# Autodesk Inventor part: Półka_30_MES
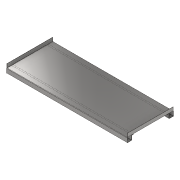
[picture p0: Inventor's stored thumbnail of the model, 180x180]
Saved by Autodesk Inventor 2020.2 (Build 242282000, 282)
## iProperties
Manager: www.cadconsulting.pl
Company: Fabian Stasiak CAD Consulting
Created: 2020-03
Part Number: Półka_30_MES
Material: Stal
Document SubType Name: Konstrukcja blachowa
Designer: F.Stasiak
Density: 7.85 g/cm^3
Sheet Metal Rule: Blacha stalowa 1.0 mm/Spoina liniowa
Appearance: Częściowo polerowany
Flat Pattern Width: 40.3896 cm
Flat Pattern Length: 68.6524 cm
Flat Pattern Area: 2772.84 cm^2
Sheet Metal Width: 403,896 mm
Sheet Metal Length: 686,524 mm
Sheet Metal Area: 277283,962 mm^2
Catalog Web Link: www.expertbooks.pl
Author: F.Stasiak
Subject: Zbiór ćwiczeń. Autodesk Inventor 2020. Kurs Professional
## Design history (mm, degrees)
node "Powierzchnia1"
  sketch "Szkic1"
    geometry: L1 (325, -125)-(-325, -125); L2 (-325, -125)-(-325, 125); L3 (-325, 125)-(325, 125); L4 (325, 125)-(325, -125); L5 (325, -125)-(-325, 125); L6 (-325, -125)-(325, 125); 1 further point
    constraints: 12 end point, 2 midpoint, 2 parallel, 1 horizontal, 1 perpendicular
    dimensions: "d0" = 650 distance of L2.end L3.end; "d1" = 250 distance of L1.end L2.end
node "Kołnierz1"
node "Kołnierz2"
node "Kołnierz3"
node "Kołnierz4"
mirror "Odbij1"
node "Kołnierz5"
sketch "Szkic11"
  geometry: L1 (0, -21)-(650, -21) reference; L2 (650, 0)-(650, -21) reference; L3 (650, 0)-(0, 0) reference; L4 (0, 0)-(0, -21) reference; L5 (650, -225)-(0, -225) reference; L6 (0, -246)-(0, -225) reference; L7 (650, -246)-(0, -246) reference; L8 (650, -246)-(650, -225) reference; L9 (0, 0)-(650, 0) reference; L10 (15, 0)-(15, -21); L11 (0, -21)-(650, -21) reference; L12 (0, -225)-(650, -225) reference; L13 (15, -225)-(15, -246); L14 (635, 0)-(635, -21); L15 (635, -225)-(635, -246); L16 (2, -246)-(648, -246) reference; 1 further point
  constraints: 8 end point, 8 point on line, 3 collinear, 2 perpendicular, 1 vertical
  dimensions: "d58" = 15 distance between parallel lines of L10 L4; "d59" = 15 distance between parallel lines of L2 L14 (= d58)
  node "Pętla rzutowana1"
  node "Pętla rzutowana2"
feature "Podział5"
feature "Podział6"
feature "Podział7"
feature "Podział8"
node "Bryła1"
feature "Płyta1" dims "d2" = 1 (= Grubość)
sketch "Szkic2"
  geometry: L1 through (-325, 0) direction (1, 0); L2 through (0, 12.5) direction (0, 1); L3 (0, 25)-(-650, 25); L4 (-650, 25)-(-650, 0)
  constraints: 6 end point, 1 horizontal, 1 perpendicular, 1 vertical
feature "Płyta2" dims "d2" = 1 (= Grubość), "d3" = 1 (= SzerokośćGięciaPodcięcia), "d4" = 0.5 (= GłębokośćGięciaPodcięcia), "d5" = 2 (= MinimalnaPozostałość), "d6" = 1 (= PromieńPrzejścia), "d9" = 25, "d10" = 90 deg, "d11" = 1 (= PromieńGięcia), "d12" = 4 (= RozmiarPodcięciaNarożnika), "d13" = 1 (= Wielk_odstępu), "d14" = 1 (= Rozmiar_promienia_Jacobiego), "OdstępPołączenia" = 0.01
feature "Zagięcie1" dims "d2" = 1 (= Grubość), "d3" = 1 (= SzerokośćGięciaPodcięcia), "d4" = 0.5 (= GłębokośćGięciaPodcięcia), "d5" = 2 (= MinimalnaPozostałość), "d6" = 1 (= PromieńPrzejścia), "d9" = 25, "d10" = 90 deg, "d11" = 1 (= PromieńGięcia), "OdstępPołączenia" = 0.01
feature "Narożnik1" dims "d9" = 25, "d10" = 90 deg, "d12" = 4 (= RozmiarPodcięciaNarożnika), "d13" = 1 (= Wielk_odstępu), "d14" = 1 (= Rozmiar_promienia_Jacobiego)
sketch "Szkic3"
  geometry: L1 (-650, 0)-(0, 0); L2 (0, 0)-(0, 25); L3 (0, 25)-(-650, 25); L4 (-650, 25)-(-650, 0)
  constraints: 8 end point
feature "Płyta3" dims "d2" = 1 (= Grubość), "d15" = 1 (= SzerokośćGięciaPodcięcia), "d16" = 0.5 (= GłębokośćGięciaPodcięcia), "d17" = 2 (= MinimalnaPozostałość), "d18" = 1 (= PromieńPrzejścia), "d19" = 25, "d20" = 90 deg, "d21" = 1 (= PromieńGięcia), "d22" = 4 (= RozmiarPodcięciaNarożnika), "d23" = 1 (= Wielk_odstępu), "d24" = 1 (= Rozmiar_promienia_Jacobiego), "OdstępPołączenia" = 0.01
feature "Zagięcie2" dims "d2" = 1 (= Grubość), "d15" = 1 (= SzerokośćGięciaPodcięcia), "d16" = 0.5 (= GłębokośćGięciaPodcięcia), "d17" = 2 (= MinimalnaPozostałość), "d18" = 1 (= PromieńPrzejścia), "d19" = 25, "d20" = 90 deg, "d21" = 1 (= PromieńGięcia), "OdstępPołączenia" = 0.01
feature "Narożnik2" dims "d19" = 25, "d20" = 90 deg, "d22" = 4 (= RozmiarPodcięciaNarożnika), "d23" = 1 (= Wielk_odstępu), "d24" = 1 (= Rozmiar_promienia_Jacobiego)
sketch "Szkic4"
  geometry: L1 through (325, 0) direction (-1, -1.88e-18); L2 through (0, -11.95) direction (1.88e-18, -1); L3 (0, -23.9)-(650, -23.9); L4 (650, -23.9)-(650, 0)
  constraints: 6 end point, 1 horizontal, 1 perpendicular, 1 vertical
feature "Płyta4" dims "d2" = 1 (= Grubość), "d25" = 1 (= SzerokośćGięciaPodcięcia), "d26" = 0.5 (= GłębokośćGięciaPodcięcia), "d27" = 2 (= MinimalnaPozostałość), "d28" = 1 (= PromieńPrzejścia), "d29" = 23.9, "d30" = 90 deg, "d31" = 1 (= PromieńGięcia), "d32" = 4 (= RozmiarPodcięciaNarożnika), "d33" = 1 (= Wielk_odstępu), "d34" = 1 (= Rozmiar_promienia_Jacobiego), "OdstępPołączenia" = 0.01
feature "Zagięcie3" dims "d2" = 1 (= Grubość), "d25" = 1 (= SzerokośćGięciaPodcięcia), "d26" = 0.5 (= GłębokośćGięciaPodcięcia), "d27" = 2 (= MinimalnaPozostałość), "d28" = 1 (= PromieńPrzejścia), "d29" = 23.9, "d30" = 90 deg, "d31" = 1 (= PromieńGięcia), "OdstępPołączenia" = 0.01
feature "Narożnik3" dims "d29" = 23.9, "d30" = 90 deg, "d32" = 4 (= RozmiarPodcięciaNarożnika), "d33" = 1 (= Wielk_odstępu), "d34" = 1 (= Rozmiar_promienia_Jacobiego)
sketch "Szkic5"
  geometry: L1 through (-325, 0) direction (1, -1.75e-18); L2 through (0, 5) direction (1.75e-18, 1); L3 (0, 10)-(-650, 10); L4 (-650, 10)-(-650, 0)
  constraints: 6 end point, 1 horizontal, 1 perpendicular, 1 vertical
feature "Płyta5" dims "d2" = 1 (= Grubość), "d35" = 1 (= SzerokośćGięciaPodcięcia), "d36" = 0.5 (= GłębokośćGięciaPodcięcia), "d37" = 2 (= MinimalnaPozostałość), "d38" = 1 (= PromieńPrzejścia), "d39" = 10, "d40" = 90 deg, "d41" = 1 (= PromieńGięcia), "d42" = 4 (= RozmiarPodcięciaNarożnika), "d43" = 1 (= Wielk_odstępu), "d44" = 1 (= Rozmiar_promienia_Jacobiego), "OdstępPołączenia" = 0.01
feature "Zagięcie4" dims "d2" = 1 (= Grubość), "d35" = 1 (= SzerokośćGięciaPodcięcia), "d36" = 0.5 (= GłębokośćGięciaPodcięcia), "d37" = 2 (= MinimalnaPozostałość), "d38" = 1 (= PromieńPrzejścia), "d39" = 10, "d40" = 90 deg, "d41" = 1 (= PromieńGięcia), "OdstępPołączenia" = 0.01
feature "Narożnik4" dims "d39" = 10, "d40" = 90 deg, "d42" = 4 (= RozmiarPodcięciaNarożnika), "d43" = 1 (= Wielk_odstępu), "d44" = 1 (= Rozmiar_promienia_Jacobiego)
sketch "Szkic6"
  geometry: L1 through (0, -123) direction (0, 1); L2 through (-10, 0) direction (-1, 0); L3 (-20, 0)-(-20, -246); L4 (-20, -246)-(0, -246)
  constraints: 6 end point, 1 horizontal, 1 perpendicular, 1 vertical
feature "Płyta6" dims "d2" = 1 (= Grubość), "d45" = 1 (= SzerokośćGięciaPodcięcia), "d46" = 0.5 (= GłębokośćGięciaPodcięcia), "d47" = 2 (= MinimalnaPozostałość), "d48" = 1 (= PromieńPrzejścia), "d49" = 20, "d50" = 90 deg, "d51" = 1 (= PromieńGięcia), "d52" = 4 (= RozmiarPodcięciaNarożnika), "d53" = 1 (= Wielk_odstępu), "d54" = 1 (= Rozmiar_promienia_Jacobiego), "OdstępPołączenia" = 0.01
feature "Zagięcie5" dims "d2" = 1 (= Grubość), "d45" = 1 (= SzerokośćGięciaPodcięcia), "d46" = 0.5 (= GłębokośćGięciaPodcięcia), "d47" = 2 (= MinimalnaPozostałość), "d48" = 1 (= PromieńPrzejścia), "d49" = 20, "d50" = 90 deg, "d51" = 1 (= PromieńGięcia), "OdstępPołączenia" = 0.01
feature "Narożnik5" dims "d49" = 20, "d50" = 90 deg, "d52" = 4 (= RozmiarPodcięciaNarożnika), "d53" = 1 (= Wielk_odstępu), "d54" = 1 (= Rozmiar_promienia_Jacobiego)
feature "Definicja1"
other parameters: "Grubość" = 1 (derived), "WspółczynnikK" = 4.4, "PromieńGięcia" = 1 (= Grubość), "SzerokośćGięciaPodcięcia" = 1 (= Grubość), "GłębokośćGięciaPodcięcia" = 0.5 (= 0.5 x Grubość), "RozmiarPodcięciaNarożnika" = 4 (= 4 x Grubość), "MinimalnaPozostałość" = 2 (= 2 x Grubość), "PromieńPrzejścia" = 1 (= PromieńGięcia), "Rozmiar_promienia_Jacobiego" = 1 (= PromieńGięcia), "Wielk_odstępu" = 1 (= Grubość), "Grubość" = 1, "GłębokośćGięciaPodcięcia" = 0.5, "MinimalnaPozostałość" = 2, "PromieńGięcia" = 1, "PromieńPrzejścia" = 1, "RozmiarPodcięciaNarożnika" = 4, "Rozmiar_promienia_Jacobiego" = 1, "SzerokośćGięciaPodcięcia" = 1, "Wielk_odstępu" = 1
